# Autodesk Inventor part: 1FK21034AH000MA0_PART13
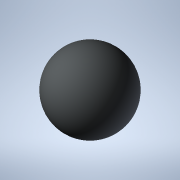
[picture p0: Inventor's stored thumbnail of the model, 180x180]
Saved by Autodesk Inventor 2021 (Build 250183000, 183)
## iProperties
Created: 2025-04
Part Number: 1FK21034AH000MA0_PART13
Material: Generic
Catalog Web Link: www.3dfindit.com
Description: -Servo synchronous motor
Document SubType Name: Modeling
Designer: psAdmin
Mass: 0.113097 g
Surface Area: 1.13097 cm^2
Volume: 0.113097 cm^3
Density: 1 g/cm^3
Appearance: PSOLRGB-212-217-219
Category: PARTsolutions
Title: 1FK21034AH000MA0_PART13
Author: Cadenas PARTsolutions
Comments: Servo synchronous motor
Sending System: PARTsolutions
Preprocessor: ST-DEVELOPER v19.3
PSOL_IDENT_0: {$CADENAS_DATA/23d-libs/siemens_ag/_cat_/ec/b7/1fk21034ah000ma0.prj},216 {VTYP=3D},{NB=1FK21034AH000
PSOL_IDENT_1: MA0_PART13},{LINA=1FK21034AH000MA0_PART13},{NN=1FK21034AH000MA0_PART13},{NOPRJ=TRUE},{DATE=19.08.202
PSOL_IDENT_2: 5 14:01:05},{GEOMDATE=30.07.2025 02:01:02},{VERSION=},{LINEID=10},{WBVAR=},{WBNUMERIC=}  {NB=1FK2103
PSOL_IDENT_3: 4AH000MA0_PART13},{LINA=1FK21034AH000MA0_PART13},{KT=DUMMY},{PREVIEW=../../../_pool_/7c/50/p_d211_xx
PSOL_IDENT_4: _00932j.png},{DESCSHORT=SIMOTICS S-1FK2 HD, SINAMICS S210 3AC 400V-480V, 1.01 Nm, 4500 rpm},{DESCLON
PSOL_IDENT_5: G=SIMOTICS S-1FK2 HD servo motor M0=1.27 Nm; PN = 0.48 kW at nN=4500 rpm (380-480 V); PN = 0.3 kW at
PSOL_IDENT_6: nN=2500 rpm (200-240 V); degree of protection IP64; cylindrical shaft D14 x 30 mm; absolute encoder
PSOL_IDENT_7: 22-bit + 12-bit multiturn (encoder AM22DQC); with OCC interface; plug size M17, rotatable; SIMOTICS
PSOL_IDENT_8: S-1FK2 servomotorfor a wide range of uses in industrial environments. SIMOTICS S‑1FK2 servomotors a
PSOL_IDENT_9: re compact synchronous motors with a high dynamic performance that set themselves apart as a result
PSOL_IDENT_10: of their high power density, degree of protection and overload capability. The motors are available
PSOL_IDENT_11: in two variants: as High Dynamic variant (highest dynamic performance as a result of the low intrins
PSOL_IDENT_12: ic moment of inertia for applications demanding a high dynamic performance with low moved masses) -
PSOL_IDENT_13: and as Compact variant (precise and stable closed-loop control for medium up to large moved masses a
PSOL_IDENT_14: s a result of a medium intrinsic moment of inertia). SIMOTICSS‑1FK2 servomotors fully exploit their
PSOL_IDENT_15: strengths in a system with the SINAMICSS210 frequency converter and simple connection using the one
PSOL_IDENT_16: cable connection (OCC). Advantages include the short control and positioning times, fast and precise
PSOL_IDENT_17: correction of disturbing quantities as well as stable control with a high dynamic performance. The
PSOL_IDENT_18: servo motors can be configured to address a wide range of requirements. For example with and without
PSOL_IDENT_19: holding brake, IP64 or IP65 degree of protection, singleturn or multiturn absolute encoders - to na
PSOL_IDENT_20: me just a few. Further, the servomotors are available in different shaft heights extending from 20 t
PSOL_IDENT_21: o 100. A shaft sealing ring is available to achieve an IP65 degree of protection and for subsequent
PSOL_IDENT_22: mounting at the motor or as spare part. SIMOTICS - the optimum motor for each and every motion contr
PSOL_IDENT_23: ol application.},{INTNO=4034106444822},{SUPPLIERALTNO=1FK2103-4AH00-0MA0},{MANUID=1FK21034AH000MA0},
PSOL_IDENT_24: {MANUNAME=Siemens},{MANUTYPEDESC=SYNCHRONOUS MOTOR 1FK2 HD 1,27 NM},{AAU732=SIMOTICS},{AAO057=S-1FK2
PSOL_IDENT_25: },{AAU734=SIMOTICS S-1FK2 HD servo motor M0=1.27 Nm; PN = 0.48 kW at nN=4500 rpm (380-480 V); PN = 0
PSOL_IDENT_26: .3 kW at nN=2500 rpm (200-240 V); degree of protection IP64; cylindrical shaft D14 x 30 mm; absolute
PSOL_IDENT_27: encoder 22-bit + 12-bit multiturn (encoder AM22DQC); with OCC interface; plug size M17, rotatable;}
PSOL_IDENT_28: ,{AAW338=SYNCHRONOUS MOTOR 1FK2 HD 1,27 NM},{AAO742=SIMOTICS},{AAO663=4034106444822},{NOCUPEROU=1},{
PSOL_IDENT_29: PRICEQUANTITY=1},{QUANTITYMIN=1},{QUANTITYINT=1},{CTN=85015100},{COO=RO},{AAO676=1FK2103-4AH00-0MA0}
PSOL_IDENT_30: ,{AAO677=Siemens AG},{ORDERUNIT=C62},{CONTENTUNIT=C62}
NB: 1FK21034AH000MA0_PART13
NT: Servo synchronous motor
NBSYN: $MANUID._PART13
LINA: 1FK21034AH000MA0_PART13
CATALOG: SIEMENS
PREVIEW: ../../../_pool_/7c/50/p_d211_xx_00932j.png
DESCSHORT: SIMOTICS S-1FK2 HD, SINAMICS S210 3AC 400V-480V, 1.01 Nm, 4500 rpm
DESCLONG: SIMOTICS S-1FK2 HD servo motor M0=1.27 Nm; PN = 0.48 kW at nN=4500 rpm (380-480 V); PN = 0.3 kW at nN=2500 rpm (200-240 V); degree of protection IP64; cylindric
INTNO: 4034106444822
SUPPLIERALTNO: 1FK2103-4AH00-0MA0
MANUID: 1FK21034AH000MA0
MANUNAME: Siemens
MANUTYPEDESC: SYNCHRONOUS MOTOR 1FK2 HD 1,27 NM
AAU732: SIMOTICS
AAO057: S-1FK2
AAU734: SIMOTICS S-1FK2 HD servo motor M0=1.27 Nm; PN = 0.48 kW at nN=4500 rpm (380-480 V); PN = 0.3 kW at nN=2500 rpm (200-240 V); degree of protection IP64; cylindric
AAW338: SYNCHRONOUS MOTOR 1FK2 HD 1,27 NM
AAO742: SIMOTICS
AAO663: 4034106444822.0
NOCUPEROU: 1
PRICEQUANTITY: 1
QUANTITYMIN: 1
QUANTITYINT: 1
CTN: 85015100
COO: RO
ARTICLENO: 1FK21034AH000MA0_PART13
BOMINFO: 1FK21034AH000MA0_PART13
CREATOR: CADENAS GmbH
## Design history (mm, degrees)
feature "2025_04_17_15_01_37_0314"
body "Solid1"
